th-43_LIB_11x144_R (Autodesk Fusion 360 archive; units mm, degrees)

design "th-43_LIB_11x144_R" references "temple_stock"
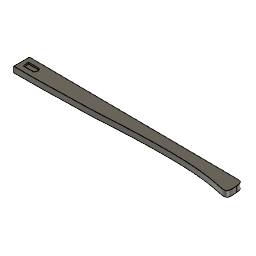
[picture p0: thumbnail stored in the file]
sketch "Temple_Right" plane through (0, 0, 0) normal (0, 0, 1) x axis (1, 0, 0)
  line L1 (0, 0) -> (3, 0)
  line L2 (10, -2) -> (3.3, -2)
  line L3 (2.7, 2) -> (3.3, -2)
  line L4 (2.7, 2) -> (10, 2)
  curve K1 (149.4284, 0) -> (0, -5.5)
  curve K2 (33.1105, -5.5) -> (-33.1105, -5.5)
  curve K3 (50.3491, -4.7282) -> (26.9792, -5.1746)
  curve K4 (137.2912, -3.2039) -> (79.9443, -2.2873)
  curve K5 (148.5188, 9.5484) -> (150.338, -9.5484)
  line L5 (146.6432, 4.3396) -> (0, 5.5)
  curve K6 (149.4284, 0) -> (145.0949, 4.3519)
  curve K7 (146.4141, 4.4073) -> (143.7756, 4.2964)
  curve K8 (149.5275, -1.268) -> (149.3294, 1.268)
  line L6 (0, -5.5) -> (0, 5.5)
  arc A1 centre (9.1115, 0) radius 2.1885 clockwise from (10, 2) to (10, -2)
  point P7 (3, 0)
  point P4 (0, 0)
  midpoint P7 L3
  horizontal L1
  vertical L6
  dimension "d27" distance P4 P7 = 3
  dimension "d22" distance = 6.1
  dimension "d23" AlongDistance = -1.1
  dimension "d24" TaperAngle = 0
extrude "Extrude7" new body sketch "Temple_Right" profile of A1 L2 L3 L4 K1 L5 K6 L6 along normal blind 4
extrude "Extrude8" add sketch "Temple_Right" profile of A1 L2 L3 L4 along normal blind 2.95
component_insert "Component Insert"

design "temple_stock"
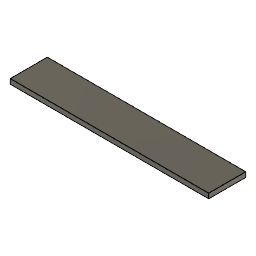
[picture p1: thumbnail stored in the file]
sketch "30mm Temple Blank" plane through (0, 0, 0) normal (0, 0, 1) x axis (1, 0, 0)
  line L1 (160, 15) -> (0, 15)
  line L2 (160, -15) -> (160, 15)
  line L3 (0, -15) -> (160, -15)
  line L4 (0, 15) -> (0, -15)
  point P2 (0, 15)
  point P3 (160, 15)
  point P5 (0, -15)
  horizontal L1
  vertical L2
  horizontal L3
  vertical L4
  dimension "d1" distance P2 P3 = 160
  dimension "d2" distance P2 P5 = 30
sketch "135mm Core Guide" plane through (0, 0, 0) normal (0, 0, 1) x axis (1, 0, 0)
  line L1 (135, 0) -> (0, 0)
  point P1 (0, 0)
  point P2 (0, 0)
  point P3 (135, 0)
  coincident P1 P2
  horizontal L1
  dimension "d4" distance P2 P3 = 135
sketch "140mm Core Guide" plane through (0, 0, 0) normal (0, 0, 1) x axis (1, 0, 0)
  line L1 (140, 0) -> (0, 0)
  point P1 (0, 0)
  point P2 (0, 0)
  point P3 (140, 0)
  coincident P1 P2
  horizontal L1
  dimension "d5" distance P2 P3 = 140
sketch "145mm Core Guide" plane through (0, 0, 0) normal (0, 0, 1) x axis (1, 0, 0)
  line L1 (145, 0) -> (0, 0)
  point P1 (0, 0)
  point P2 (0, 0)
  point P3 (145, 0)
  coincident P1 P2
  horizontal L1
  dimension "d6" distance P2 P3 = 145
extrude "Extrude1" new body sketch "30mm Temple Blank" along normal blind 4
